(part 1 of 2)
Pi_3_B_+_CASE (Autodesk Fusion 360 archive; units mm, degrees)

design "Pi_3_B_+" references "Pi 3 B +"
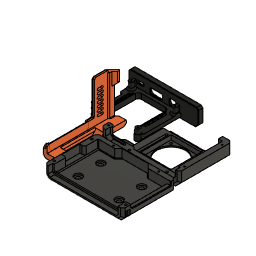
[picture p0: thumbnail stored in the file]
parameter "d10_Ref" = 24.193
parameter "d16_Ref" = 27.166
parameter "d18_Ref" = 29.088
parameter "d23_Ref" = -3
parameter "d27_Ref" = 6
parameter "d28_Ref" = 0
parameter "d52_Ref" = -1.4
parameter "d61_Ref" = -0.4
parameter "d62_Ref" = -1.053
parameter "d63_Ref" = -2
parameter "d65_Ref" = 0.172
parameter "d66_Ref" = -5
parameter "d67_Ref" = -2
parameter "d68_Ref" = -1
parameter "d89_Ref" = 0.75
parameter "d90_Ref" = 45 (= "Angle1")
parameter "d91_Ref" = 0 (= "Angle2")
parameter "d93_Ref" = -0.2
parameter "d94_Ref" = -0.1
parameter "d96_Ref" = 2
parameter "d103_Ref" = -0.1
parameter "d105_Ref" = -0.1
parameter "d106_Ref" = -0.1
parameter "d107_Ref" = -0.1
parameter "d109_Ref" = 2.6
parameter "d111_Ref" = 2.5
parameter "d112_Ref" = -0.1
parameter "d114_Ref" = -3
parameter "d116_Ref" = 0.5
parameter "d118_Ref" = 2
parameter "d119_Ref" = 5
parameter "d121_Ref" = -1
parameter "d122_Ref" = -2
parameter "d124_Ref" = 0.5
parameter "d128_Ref" = 2
parameter "d131_Ref" = 0.4
parameter "d132_Ref" = 0.5
parameter "d133_Ref" = 1
parameter "d134_Ref" = 3
parameter "d135_Ref" = 2.8
parameter "d147_Ref" = -0.4
parameter "d149_Ref" = -0.2
parameter "d151_Ref" = 0.4
parameter "d153_Ref" = 0.4
parameter "d155_Ref" = -0.2
parameter "d156_Ref" = -0.2
parameter "d157_Ref" = 0.399
parameter "d159_Ref" = 5
parameter "d161_Ref" = 45 (= "Angle1")
parameter "d162_Ref" = 0 (= "Angle2")
parameter "d163_Ref" = 45 (= "Angle1")
parameter "d164_Ref" = 0 (= "Angle2")
parameter "d165_Ref" = 2.5
parameter "d166_Ref" = 3
parameter "d167_Ref" = 3
parameter "d168_Ref" = 2.5
parameter "d169_Ref" = 1
parameter "d170_Ref" = 1
parameter "d171_Ref" = 1
parameter "d172_Ref" = 3
parameter "d173_Ref" = 1
parameter "d174_Ref" = 1
parameter "d206_Ref" = 0.4
parameter "d207_Ref" = 0.4
parameter "d208_Ref" = 8
parameter "d212_Ref" = 10
parameter "d213_Ref" = 3.3
parameter "d215_Ref" = -2
parameter "d217_Ref" = 0.5
parameter "d218_Ref" = 0.3
parameter "d219_Ref" = 0.3
parameter "d226_Ref" = -0.8
parameter "d227_Ref" = 10
parameter "d229_Ref" = 2.5
parameter "d232_Ref" = 2.5
parameter "d233_Ref" = 2
parameter "d239_Ref" = -8
parameter "d241_Ref" = 0.5
parameter "d242_Ref" = -3.536
parameter "d243_Ref" = 3
parameter "d12_Ref" = 20.9455
parameter "d14_Ref" = 28.705
parameter "d31_Ref" = 10
parameter "d32_Ref" = 2
parameter "d34_Ref" = 3
parameter "d35_Ref" = 20
parameter "d44_Ref" = -3
parameter "d49_Ref" = -11.7
parameter "d51_Ref" = 3
parameter "d53_Ref" = 3
parameter "d55_Ref" = 2
parameter "d57_Ref" = -1
parameter "d58_Ref" = 1
parameter "d60_Ref" = -0.4
parameter "d69_Ref" = 2.5
parameter "d70_Ref" = -1
parameter "d85_Ref" = 0.8
parameter "d86_Ref" = 0.75
parameter "d88_Ref" = 0.75
parameter "d152_Ref" = 0.3
parameter "d21_Ref" = 20.935
parameter "d38_Ref" = 60
parameter "d39_Ref" = 0
parameter "d40_Ref" = -5
parameter "d42_Ref" = -3.933
parameter "d43_Ref" = -1
parameter "d45_Ref" = 1
parameter "d56_Ref" = 1.4
parameter "d71_Ref" = 0.4
parameter "d75_Ref" = 2
parameter "d76_Ref" = 0.75
parameter "d77_Ref" = 1
parameter "d79_Ref" = -1
parameter "d80_Ref" = 1
parameter "d83_Ref" = 0.75
parameter "d84_Ref" = 0.75
parameter "d87_Ref" = 0.75
parameter "d92_Ref" = 0.2
parameter "d95_Ref" = 2
parameter "d98_Ref" = 2
parameter "d101_Ref" = 0.6
parameter "d102_Ref" = 2.6
parameter "d104_Ref" = 2
parameter "d220_Ref" = 2
parameter "d221_Ref" = 3
parameter "d222_Ref" = 0.2
parameter "d224_Ref" = 0.5
parameter "d225_Ref" = 0.8
parameter "d2_1_Ref" = 180
parameter "d3_Ref" = 180
parameter "d6_Ref" = 5
parameter "d7_Ref" = 5
parameter "d8_Ref" = 0
parameter "d59_Ref" = -1
parameter "d140_Ref" = 7.375
parameter "d141_Ref" = 2
parameter "d178_Ref" = -4.3752
parameter "d180_Ref" = 1.1
parameter "d181_Ref" = -4.3752
parameter "d183_Ref" = -0.1
parameter "d184_Ref" = 1
parameter "d185_Ref" = -2.291
parameter "d187_Ref" = 4
parameter "d188_Ref" = -1.625
parameter "d190_Ref" = 0
parameter "d191_Ref" = 10.23
parameter "d193_Ref" = 10
parameter "d194_Ref" = 2
parameter "d196_Ref" = 10
parameter "d197_Ref" = 2
parameter "d199_Ref" = 10
parameter "d200_Ref" = 2
parameter "d202_Ref" = 10
parameter "d203_Ref" = 2
parameter "d205_Ref" = 1
parameter "d261_Ref" = -10.895
parameter "d262_Ref" = -4.25
parameter "d263_Ref" = 2
parameter "d267_Ref" = -35
parameter "d268_Ref" = 0
parameter "d269_Ref" = 0.3
parameter "d287_Ref" = -5
parameter "d289_Ref" = 0.3
parameter "d292_Ref" = 35
parameter "d293_Ref" = 0
parameter "d294_Ref" = 0.3
parameter "d244_Ref" = 1
parameter "d250_Ref" = 6.4
parameter "d251_Ref" = 2
external_derived "ExternalDerived1" bodies "PI3 A/B_MOUNT  (1) (2)", "Body4", "TOP", "BOTTOM"
derived_instance "DerivedInstance1"
derived_instance "DerivedInstance2"
derived_instance "DerivedInstance3"
derived_instance "DerivedInstance4"
derived_instance "DerivedInstance1"
step "Arrange" envelopeLength 180 envelopeWidth 180 envelopeSeparation 0 separation 5 padding 5 offset 0
hole "Hole2" HoleDepth 5 HoleDiameter 5.3 CBDepth 2 CBDiameter 10 RefDim1 25 RefDim2 20
hole "Hole4" HoleDepth 5 HoleDiameter 5.3 CBDepth 2 CBDiameter 10 RefDim1 20 RefDim2 25
rectangular_pattern "R-Pattern2" uSpaceDistance 30 vSpaceDistance 0 bodies "BOTTOM"
rectangular_pattern "R-Pattern3" uSpaceDistance 30 vSpaceDistance 0 bodies "BOTTOM"
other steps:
derived_base_feature "Derived Base Feature1" bodies "BOTTOM"
derived_base_feature "Derived Base Feature1" bodies "Body4", "BOTTOM"
derived_base_feature "Derived Base Feature1" bodies "TOP", "BOTTOM"
derived_base_feature "Derived Base Feature1" bodies "PI3 A/B_MOUNT  (1) (2)", "BOTTOM"
derived_base_feature "Derived Base Feature1" bodies "BOTTOM"
create_component "CreateComponent1"
create_component "CreateComponent2"
create_component "CreateComponent3"
create_component "CreateComponent4"
create_component "CreateComponent5"
named bodies: "TOP", "BOTTOM", "PI3 A/B_MOUNT  (1) (2)", "Body4"

design "M3x5x4 heat-Insert"
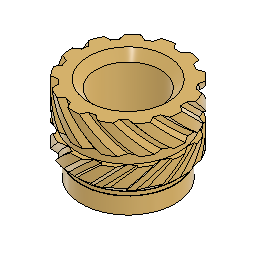
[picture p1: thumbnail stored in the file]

design "Pi 3 B +" references "M3x5x4 heat-Insert"
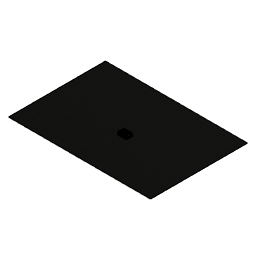
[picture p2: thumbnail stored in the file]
description: arrangementsContainer
base_feature "Base Feature1" bodies "TOP"
base_feature "Base Feature1" bodies "BOTTOM"
base_feature "Base Feature1"
base_feature "Base Feature1"
base_feature "Base Feature1"
base_feature "Base Feature1"
base_feature "Base Feature1"
base_feature "Base Feature1"
base_feature "Base Feature1"
base_feature "Base Feature1"
position "Position1"
sketch "Sketch1" plane through (0, 0, 0) normal (0, 0, 1) x axis (1, 0, 0)
  line L1 (753.1049, -468.8034) -> (-832.4959, -468.8034)
  line L2 (753.1049, 612.7156) -> (753.1049, -468.8034)
  line L3 (-832.4959, 612.7156) -> (753.1049, 612.7156)
  line L4 (-832.4959, -468.8034) -> (-832.4959, 612.7156)
  horizontal L1
  vertical L2
  horizontal L3
  vertical L4
extrude "Extrude1" new body sketch "Sketch1" against normal blind 1 bodies "base"
base_feature "Base Feature1" bodies "PI3 A/B_MOUNT  (1) (2)"
component_from_bodies "Body->Comp"
step "Arrange" envelopeLength 180 named "d2_1" envelopeWidth 180 envelopeSeparation 0 separation 5 padding 5 offset 0 bodies "TOP"
base_feature "Base Feature1"
position "Position2"
position "Position3"
delete_face "DeleteFace1"
base_feature "Base Feature1" bodies "PI_ZERO_MOUNT_1"
move_face "MoveFace1"
work_plane "WorkPlane2"
split "Split1" bodies "TOP (1)"
move "Move1"
move "Move2"
position "Position4"
align "Align1"
move "Move3"
extrude "Extrude1" add of existing geometry blind 24.193 bodies "TOP (1)"
delete_face "DeleteFace2"
delete_face "DeleteFace3"
delete_face "DeleteFace4"
align "Align1"
work_plane "WorkPlane3"
split "Split1" bodies "BOTTOM (1)"
move "Move1"
align "Align2"
move "Move2"
move "Move3"
extrude "Extrude1" add of existing geometry blind 20.9455 bodies "BOTTOM (1)"
work_plane "WorkPlane4"
split "Split2" bodies "BOTTOM (1)"
delete_face "DeleteFace1"
move "Move4"
split "Split2"
move "Move4"
align "Align3"
align "Align4"
align "Align1"
align "Align1"
delete_face "DeleteFace2"
delete_face "DeleteFace3"
extrude "Extrude2" add of existing geometry blind 28.705 bodies "BOTTOM (1)"
extrude "Extrude2" add of existing geometry blind 27.166 bodies "TOP"
extrude "Extrude3" add of existing geometry blind 29.088
align "Align1"
align "Align2"
align "Align3"
align "Align1"
align "Align1"
align "Align1"
align "Align1"
align "Align1"
work_plane "WorkPlane5" AlongDistance -25
split "Split1"
align "Align4"
extrude "Extrude1" add of existing geometry blind 20.935
move_face "MoveFace1"
move_face "MoveFace2"
move_face "MoveFace2"
delete_face "DeleteFace1"
delete_face "DeleteFace2"
sketch "Sketch3" plane through (0, 0, 18.6752) normal (0, 0, -1) x axis (1, 0, 0)
  line L1 (-40.9922, -30.131) -> (-40.9922, 26.269)
  line L2 (-39.8593, -30.131) -> (-40.9922, -30.131)
  line L3 (-39.8593, -21.931) -> (-39.8593, -30.131)
  line L4 (-37.6593, -19.731) -> (-39.8593, -21.931)
  line L5 (37.1513, -19.731) -> (-37.6593, -19.731)
  line L6 (37.9797, -18.9025) -> (37.1513, -19.731)
  line L7 (37.9797, 16.5519) -> (37.9797, -18.9025)
  line L8 (40.6719, 19.2441) -> (37.9797, 16.5519)
  line L9 (40.6719, 26.269) -> (40.6719, 19.2441)
  line L10 (4.9368, 26.269) -> (40.6719, 26.269)
  line L11 (6.4368, -14.231) -> (6.4368, 24.769)
  line L12 (3.4368, 24.769) -> (3.4368, -14.231)
  line L13 (-0.0632, 26.269) -> (4.9368, 26.269)
  line L14 (1.4368, -14.231) -> (1.4368, 24.769)
  line L15 (-1.5632, 24.769) -> (-1.5632, -14.231)
  line L16 (-5.0632, 26.269) -> (-0.0632, 26.269)
  line L17 (-3.5632, -15.231) -> (-3.5632, 24.769)
  line L18 (-6.5632, 24.769) -> (-6.5632, -15.231)
  line L19 (-10.0633, 26.269) -> (-5.0632, 26.269)
  line L20 (-9.9796, 26.2667) -> (-9.9797, 26.2667)
  line L21 (-8.5632, -17.231) -> (-8.5632, 24.769)
  line L22 (-9.9797, -18.7286) -> (-9.9796, -18.7286)
  line L23 (-11.5633, 24.769) -> (-11.5633, -17.231)
  line L24 (-15.0633, 26.269) -> (-10.0633, 26.269)
  line L25 (-13.5633, -17.231) -> (-13.5633, 24.769)
  line L26 (-16.5633, 24.769) -> (-16.5633, -17.231)
  line L27 (-20.0633, 26.269) -> (-15.0633, 26.269)
  line L28 (-18.5633, -15.231) -> (-18.5633, 24.769)
  line L29 (-21.5633, 24.769) -> (-21.5633, -15.231)
  line L30 (-25.0633, 26.269) -> (-20.0633, 26.269)
  line L31 (-23.5633, -14.231) -> (-23.5633, 24.769)
  line L32 (-26.5633, 24.769) -> (-26.5633, -14.231)
  line L33 (-30.0633, 26.269) -> (-25.0633, 26.269)
  line L34 (-28.5633, -14.231) -> (-28.5633, 24.769)
  line L35 (-31.5633, 24.769) -> (-31.5633, -14.231)
  line L36 (-35.0633, 26.269) -> (-30.0633, 26.269)
  line L37 (-33.5633, -14.231) -> (-33.5633, 24.769)
  line L38 (-36.5633, 24.769) -> (-36.5633, -14.231)
  line L39 (-40.9922, 26.269) -> (-35.0633, 26.269)
  line L40 (-32.6085, -18.7224) -> (10.2712, -18.7224)
  line L41 (-32.6085, 24.769) -> (-32.6085, -18.7224)
  line L42 (10.2712, 24.769) -> (-32.6085, 24.769)
  line L43 (10.2712, -18.7224) -> (10.2712, 24.769)
  arc A1 centre (4.9368, 24.769) radius 1.5 clockwise from (4.9368, 26.269) to (6.4368, 24.769)
  arc A2 centre (4.9368, -14.231) radius 1.5 clockwise from (6.4368, -14.231) to (3.4368, -14.231)
  arc A3 centre (4.9368, 24.769) radius 1.5 clockwise from (3.4368, 24.769) to (4.9368, 26.269)
  arc A4 centre (-0.0632, 24.769) radius 1.5 clockwise from (-0.0632, 26.269) to (1.4368, 24.769)
  arc A5 centre (-0.0632, -14.231) radius 1.5 clockwise from (1.4368, -14.231) to (-1.5632, -14.231)
  arc A6 centre (-0.0632, 24.769) radius 1.5 clockwise from (-1.5632, 24.769) to (-0.0632, 26.269)
  arc A7 centre (-5.0632, 24.769) radius 1.5 clockwise from (-5.0632, 26.269) to (-3.5632, 24.769)
  arc A8 centre (-5.0632, -15.231) radius 1.5 clockwise from (-3.5632, -15.231) to (-6.5632, -15.231)
  arc A9 centre (-5.0632, 24.769) radius 1.5 clockwise from (-6.5632, 24.769) to (-5.0632, 26.269)
  arc A10 centre (-10.0633, 24.769) radius 1.5 clockwise from (-10.0633, 26.269) to (-9.9797, 26.2667)
  arc A11 centre (-10.0632, 24.769) radius 1.5 clockwise from (-9.9796, 26.2667) to (-8.5632, 24.769)
  arc A12 centre (-10.0632, -17.231) radius 1.5 clockwise from (-8.5632, -17.231) to (-9.9796, -18.7286)
  arc A13 centre (-10.0633, -17.231) radius 1.5 clockwise from (-9.9797, -18.7286) to (-11.5633, -17.231)
  arc A14 centre (-10.0633, 24.769) radius 1.5 clockwise from (-11.5633, 24.769) to (-10.0633, 26.269)
  arc A15 centre (-15.0633, 24.769) radius 1.5 clockwise from (-15.0633, 26.269) to (-13.5633, 24.769)
  arc A16 centre (-15.0633, -17.231) radius 1.5 clockwise from (-13.5633, -17.231) to (-16.5633, -17.231)
  arc A17 centre (-15.0633, 24.769) radius 1.5 clockwise from (-16.5633, 24.769) to (-15.0633, 26.269)
  arc A18 centre (-20.0633, 24.769) radius 1.5 clockwise from (-20.0633, 26.269) to (-18.5633, 24.769)
  arc A19 centre (-20.0633, -15.231) radius 1.5 clockwise from (-18.5633, -15.231) to (-21.5633, -15.231)
  arc A20 centre (-20.0633, 24.769) radius 1.5 clockwise from (-21.5633, 24.769) to (-20.0633, 26.269)
  arc A21 centre (-25.0633, 24.769) radius 1.5 clockwise from (-25.0633, 26.269) to (-23.5633, 24.769)
  arc A22 centre (-25.0633, -14.231) radius 1.5 clockwise from (-23.5633, -14.231) to (-26.5633, -14.231)
  arc A23 centre (-25.0633, 24.769) radius 1.5 clockwise from (-26.5633, 24.769) to (-25.0633, 26.269)
  arc A24 centre (-30.0633, 24.769) radius 1.5 clockwise from (-30.0633, 26.269) to (-28.5633, 24.769)
  arc A25 centre (-30.0633, -14.231) radius 1.5 clockwise from (-28.5633, -14.231) to (-31.5633, -14.231)
  arc A26 centre (-30.0633, 24.769) radius 1.5 clockwise from (-31.5633, 24.769) to (-30.0633, 26.269)
  arc A27 centre (-35.0633, 24.769) radius 1.5 clockwise from (-35.0633, 26.269) to (-33.5633, 24.769)
  arc A28 centre (-35.0633, -14.231) radius 1.5 clockwise from (-33.5633, -14.231) to (-36.5633, -14.231)
  arc A29 centre (-35.0633, 24.769) radius 1.5 clockwise from (-36.5633, 24.769) to (-35.0633, 26.269)
  horizontal L40
  vertical L41
  horizontal L42
  vertical L43
extrude "Extrude4" add sketch "Sketch3" profile of L11 A2 L12 L14 A5 L15 L17 A8 L18 L21 A12 A13 L23 L25 A16 L26 L28 A19 L29 L31 A22 L32 L34 A25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 against normal blind 3
delete_face "DeleteFace3"
delete_face "DeleteFace4"
delete_face "DeleteFace5"
delete_face "DeleteFace6"
delete_face "DeleteFace7"
delete_face "DeleteFace8"
rectangular_pattern "R-Pattern1" uSpaceDistance 6 vSpaceDistance 0
position "Position5"
work_plane "WorkPlane6" AlongDistance 2
work_plane "WorkPlane7" AlongDistance 2
move_face "MoveFace1"
move_face "MoveFace2"
move_face "MoveFace3"
hole "Hole1" HoleDepth 10 HoleDiameter 2 RefDim1 3 RefDim2 20
work_axis "WorkAxis1"
move_face "MoveFace4"
work_axis "WorkAxis3"
move_face "MoveFace3"
rectangular_pattern "R-Pattern1" uSpaceDistance 60 vSpaceDistance 0
position "Position6"
position "Position7"
delete_face "DeleteFace1"
delete_face "DeleteFace2"
delete_face "DeleteFace3"
extrude "Extrude2" cut of existing geometry blind -5
delete_face "DeleteFace4"
offset_faces "OffsetFaces1" distance -3.933
offset_faces "OffsetFaces2" distance -1
move_face "MoveFace4"
delete_face "DeleteFace5"
delete_face "DeleteFace4"
delete_face "DeleteFace5"
delete_face "DeleteFace6"
offset_faces "OffsetFaces1" distance -3
delete_face "DeleteFace7"
chamfer "Chamfer2" distance 1
work_plane "WorkPlane8" AlongDistance 1
move_face "MoveFace2"
move_face "MoveFace5"
work_plane "WorkPlane9" AlongDistance 0
sketch "Sketch4" plane through (0, 0, 16.7) normal (0, 0, 1) x axis (-1, 0, 0)
  line L1 (-45.1398, 29) -> (-45.1398, 24.4)
  line L2 (-45.7598, 29) -> (-45.1398, 29)
  line L3 (-45.7598, 35) -> (-45.7598, 29)
  line L4 (-49.1398, 35) -> (-45.7598, 35)
  line L5 (-52.1398, 32) -> (-49.1398, 35)
  line L6 (-52.1398, 21.7542) -> (-52.1398, 32)
  line L7 (-49.1398, 20) -> (-49.1398, 25)
  line L8 (-52.1398, -32) -> (-52.1398, 22.2)
  line L9 (-52.1398, 20) -> (-49.1398, 20)
  line L10 (-45.1398, 20) -> (-45.1398, 24.4)
  line L11 (-49.1398, 20) -> (-45.1398, 20)
  circle C1 centre (-49.1398, 25) radius 1.4
  arc A1 centre (-49.1398, 24.4) radius 4 clockwise from (-45.1398, 24.4) to (-52.1398, 21.7542)
  point P2 (-49.1398, 25)
  point P11 (-49.1398, 25)
  point P15 (-52.1398, 20)
  point P3 (-45.1398, 24.4)
  point P16 (-45.1398, 24.4)
  point P12 (-49.1398, 20)
  coincident P2 P11
  vertical L7
  coincident L8 P15
  perpendicular L8 L9
  coincident P3 P16
  perpendicular L9 L10
  perpendicular L7 L11
  dimension "d48" distance P11 P12 = 5
extrude "Extrude3" add sketch "Sketch4" profile of A1 L7 L10 L11 against normal blind 11.7
offset_faces "OffsetFaces2" distance 3
delete_face "DeleteFace8"
delete_face "DeleteFace9"
move_face "MoveFace6"
delete_face "DeleteFace10"
delete_face "DeleteFace11"
delete_face "DeleteFace12"
move_face "MoveFace7"
work_axis "WorkAxis4"
move_face "MoveFace4"
offset_faces "OffsetFaces1" distance -1.4
chamfer "Chamfer2" distance 3
fillet "Fillet1" radius 2
offset_faces "OffsetFaces3" distance 1.4
offset_faces "OffsetFaces3" distance -1
offset_faces "OffsetFaces4" distance 1
position "Position8"
offset_faces "OffsetFaces1" distance -1
offset_faces "OffsetFaces5" distance -0.4
offset_faces "OffsetFaces3" distance -1.053
sketch "Sketch5" plane through (0, -27, 0) normal (0, 1, 0) x axis (-1, 0, 0)
  line L1 (-40.8321, 30.4) -> (-13.0969, 30.4)
  line L2 (-45.1398, 26.0922) -> (-40.8321, 30.4)
  line L3 (-45.1398, 24.753) -> (-45.1398, 26.0922)
  line L4 (-41.3928, 28.5) -> (-45.1398, 24.753)
  line L5 (39.9036, 28.5) -> (-41.3928, 28.5)
  line L6 (45.1398, 23.2638) -> (39.9036, 28.5)
  line L7 (45.1398, 26.0922) -> (45.1398, 23.2638)
  line L8 (40.8321, 30.4) -> (45.1398, 26.0922)
  line L9 (34.9031, 30.4) -> (40.8321, 30.4)
  line L10 (28.9031, 30.4) -> (34.9031, 30.4)
  line L11 (22.9031, 30.4) -> (28.9031, 30.4)
  line L12 (16.9031, 30.4) -> (22.9031, 30.4)
  line L13 (10.9031, 30.4) -> (16.9031, 30.4)
  line L14 (4.9031, 30.4) -> (10.9031, 30.4)
  line L15 (-1.0969, 30.4) -> (4.9031, 30.4)
  line L16 (-7.0969, 30.4) -> (-1.0969, 30.4)
  line L17 (-13.0969, 30.4) -> (-7.0969, 30.4)
  line L18 (-21.1686, 27.0881) -> (-42.8047, 27.0881)
  line L19 (-21.0388, 27.4) -> (-20.0388, 28.4)
  line L20 (-20.5388, 27.9) -> (-20.0388, 28.4)
  line L21 (-22.4602, 25.9787) -> (-20.5388, 27.9)
  line L22 (-21.0388, 27.4) -> (-22.4602, 25.9787)
  line L23 (-45.1398, 24.753) -> (-41.3928, 28.5)
  line L24 (39.9036, 28.5) -> (-41.3928, 28.5)
  line L25 (-41.4928, 28.4) -> (-20.0388, 28.4)
  point P19 (-42.8047, 27.0881)
  point P21 (-20.0388, 28.4)
  point P28 (-20.0388, 28.4)
  point P29 (-41.4928, 28.4)
  coincident L4 P19
  parallel L5 L18
  coincident P21 P28
  coincident L23 P29
  parallel L24 L25
extrude "Extrude5" add sketch "Sketch5" profile of L4 L18 L19 L20 L21 L22 L23 L25 against normal blind 2
offset_faces "OffsetFaces4" distance 0.172
offset_faces "OffsetFaces5" distance -5
delete_face "DeleteFace9"
offset_faces "OffsetFaces6" distance -2
offset_faces "OffsetFaces7" distance -1
chamfer "Chamfer3" distance 2.5
offset_faces "OffsetFaces6" distance -1
move_face "MoveFace3"
move_face "MoveFace4"
move_face "MoveFace5"
position "Position9"
offset_faces "OffsetFaces4" distance 0.4
sketch "Sketch6" plane through (0, -24.4, 0) normal (0, 1, 0) x axis (-1, 0, 0)
  line L1 (-44.9031, 33.4) -> (-40.0398, 33.4)
  line L2 (-52.1398, 26.1633) -> (-44.9031, 33.4)
  line L3 (-52.1398, 16.7) -> (-52.1398, 26.1633)
  line L4 (-47.1398, 16.7) -> (-52.1398, 16.7)
  line L5 (-47.1398, 26.9206) -> (-47.1398, 16.7)
  line L6 (-43.6605, 30.4) -> (-47.1398, 26.9206)
  line L7 (-38.1398, 30.4) -> (-43.6605, 30.4)
  line L8 (-38.1398, 31.6) -> (-38.1398, 30.4)
  line L9 (-40.0398, 31.6) -> (-38.1398, 31.6)
  line L10 (-40.0398, 33.4) -> (-40.0398, 31.6)
  line L11 (-51.3825, 26.9206) -> (-47.1398, 26.9206)
  line L12 (-47.1398, 29.0252) -> (-42.2068, 29.0252)
  line L13 (-49.2779, 29.0252) -> (-47.1398, 29.0252)
  line L14 (-49.2779, 29.0252) -> (-49.2779, 29.0252)
  line L15 (-42.2068, 29.0252) -> (-49.2779, 29.0252)
  line L16 (-42.2068, 29.0252) -> (-42.2068, 29.0252)
  point P7 (-47.1398, 26.9206)
  point P12 (-47.1398, 26.9206)
  point P13 (-51.3825, 26.9206)
  coincident P7 P12
  coincident L2 P13
  perpendicular L5 L11
extrude "Extrude2" new body sketch "Sketch6" profile of L2 L6 L11 L12 L13 L15 blind 15 from offset 0.1
combine "Combine1"
chamfer "Chamfer3" distance 2
delete_face "DeleteFace6"
offset_faces "OffsetFaces5" distance 0.75
extrude "Extrude3" add of existing geometry blind 1
delete_face "DeleteFace7"
offset_faces "OffsetFaces6" distance -1
extrude "Extrude4" add of existing geometry blind 1
delete_face "DeleteFace8"
delete_face "DeleteFace9"
delete_face "DeleteFace10"
chamfer "Chamfer5" distance 0.75
delete_face "DeleteFace11"
delete_face "DeleteFace12"
delete_face "DeleteFace13"
chamfer "Chamfer6" distance 0.75
offset_faces "OffsetFaces7" distance 0.8
delete_face "DeleteFace14"
chamfer "Chamfer4" distance 0.75
chamfer "Chamfer7" distance 0.75
split "Split3" bodies "TOP (1) (1)", "TOP (1) (2)"
chamfer "Chamfer5" distance 0.75
combine "Combine1" bodies "TOP (1) (1)", "TOP (1) (2)"
draft "Draft1" "d90" 45 (= "Angle1") "d91" 0 (= "Angle2")
combine "Combine2"
offset_faces "OffsetFaces7" distance 0.2
offset_faces "OffsetFaces8" distance -0.2
move_face "MoveFace5"
move_face "MoveFace5"
offset_faces "OffsetFaces9" distance -0.1
chamfer "Chamfer8" distance 2
chamfer "Chamfer3" distance 2
sketch "Sketch7" plane through (0, -24.3, 0) normal (0, -1, 0) x axis (1, 0, 0)
  line L1 (25.1398, 30.4) -> (25.1398, 31.6)
  line L2 (40.8321, 30.4) -> (25.1398, 30.4)
  line L3 (41.2068, 30.0252) -> (40.8321, 30.4)
  line L4 (44.0353, 30.0252) -> (41.2068, 30.0252)
  line L5 (45.0353, 29.0252) -> (44.0353, 30.0252)
  line L6 (47.8898, 26.1706) -> (45.0353, 29.0252)
  line L7 (47.8898, 25.1706) -> (47.8898, 26.1706)
  line L8 (51.3825, 25.1706) -> (47.8898, 25.1706)
  line L9 (52.1325, 25.9206) -> (51.3825, 25.1706)
  line L10 (52.1325, 26.1706) -> (52.1325, 25.9206)
  line L11 (44.9031, 33.4) -> (52.1325, 26.1706)
  line L12 (27.0398, 33.4) -> (44.9031, 33.4)
  line L13 (27.0398, 31.6) -> (27.0398, 33.4)
  line L14 (25.1398, 31.6) -> (27.0398, 31.6)
  line L15 (40.1398, 31.6) -> (25.1398, 31.6)
  line L16 (40.1398, 30.4) -> (40.1398, 31.6)
  line L17 (25.1398, 30.4) -> (40.1398, 30.4)
  line L18 (25.1398, 31.6) -> (25.1398, 30.4)
  point P2 (25.1398, 31.6)
  point P16 (25.1398, 31.6)
  point P17 (40.1398, 31.6)
  horizontal L15
  vertical L16
  horizontal L17
  vertical L18
  coincident P2 P16
  dimension "d97" distance P16 P17 = 15
extrude "Extrude5" add sketch "Sketch7" profile of L1 L2 L14 L15 L16 L17 L18 along normal blind 2
delete_face "DeleteFace15"
delete_face "DeleteFace16"
delete_face "DeleteFace17"
delete_face "DeleteFace18"
offset_faces "OffsetFaces8" distance 0.6
chamfer "Chamfer10" distance 2.6
combine "Combine2"
offset_faces "OffsetFaces10" distance -0.1
offset_faces "OffsetFaces9" distance 2
combine "Combine3"
offset_faces "OffsetFaces11" distance -0.1
offset_faces "OffsetFaces12" distance -0.1
offset_faces "OffsetFaces13" distance -0.1
sketch "Sketch8" plane through (0, -27, 0) normal (0, 1, 0) x axis (-1, 0, 0)
  line L1 (-40.4097, 31.7) -> (-25.0398, 31.7)
  line L2 (-40.4097, 30.4) -> (-40.4097, 31.7)
  line L3 (-43.6605, 30.4) -> (-40.4097, 30.4)
  line L4 (-45.1398, 28.9206) -> (-43.6605, 30.4)
  line L5 (-45.1398, 26.1672) -> (-45.1398, 28.9206)
  line L6 (-44.2189, 27.0881) -> (-45.1398, 26.1672)
  line L7 (-28.4218, 27.0881) -> (-44.2189, 27.0881)
  line L8 (-27.0099, 28.5) -> (-28.4218, 27.0881)
  line L9 (39.9036, 28.5) -> (-27.0099, 28.5)
  line L10 (45.1398, 23.2638) -> (39.9036, 28.5)
  line L11 (45.1398, 26.0922) -> (45.1398, 23.2638)
  line L12 (40.8321, 30.4) -> (45.1398, 26.0922)
  line L13 (34.9031, 30.4) -> (40.8321, 30.4)
  line L14 (28.9031, 30.4) -> (34.9031, 30.4)
  line L15 (22.9031, 30.4) -> (28.9031, 30.4)
  line L16 (16.9031, 30.4) -> (22.9031, 30.4)
  line L17 (10.9031, 30.4) -> (16.9031, 30.4)
  line L18 (4.9031, 30.4) -> (10.9031, 30.4)
  line L19 (-1.0969, 30.4) -> (4.9031, 30.4)
  line L20 (-7.0969, 30.4) -> (-1.0969, 30.4)
  line L21 (-13.0969, 30.4) -> (-7.0969, 30.4)
  line L22 (-25.0398, 30.4) -> (-13.0969, 30.4)
  line L23 (-25.0398, 31.7) -> (-25.0398, 30.4)
  line L24 (-18.6605, 30.4) -> (-43.6605, 30.4)
  line L25 (-18.6605, 28.5) -> (-18.6605, 30.4)
  line L26 (-45.5605, 28.5) -> (-18.6605, 28.5)
  line L27 (-43.6605, 30.4) -> (-45.5605, 28.5)
  point P5 (-43.6605, 30.4)
  point P25 (-43.6605, 30.4)
  point P27 (-18.6605, 28.5)
  point P26 (-18.6605, 30.4)
  coincident P5 P25
  parallel L22 L24
  coincident L9 P27
  perpendicular L9 L25
  perpendicular L5 L26
  parallel L4 L27
  dimension "d108" distance P25 P26 = 25
extrude "Extrude6" add sketch "Sketch8" profile of L3 L4 L5 L9 L22 L24 L25 L26 L27 along normal blind 2.6
delete_face "DeleteFace10"
chamfer "Chamfer4" distance 2.5
delete_face "DeleteFace11"
offset_faces "OffsetFaces14" distance -0.1
sketch "Sketch9" plane through (0, 0, 33.4) normal (0, 0, 1) x axis (-1, 0, 0)
  line L1 (-24.9398, -18.9172) -> (-24.9398, 22.4)
  line L2 (-22.957, -20.9) -> (-24.9398, -18.9172)
  line L3 (36.5406, -20.9) -> (-22.957, -20.9)
  line L4 (39.6992, -24.0586) -> (36.5406, -20.9)
  line L5 (39.6992, -32) -> (39.6992, -24.0586)
  line L6 (44.9031, -32) -> (39.6992, -32)
  line L7 (44.9031, 32) -> (44.9031, -32)
  line L8 (34.6979, 32) -> (44.9031, 32)
  line L9 (34.6979, 31) -> (34.6979, 32)
  line L10 (28.8979, 32) -> (28.8979, 31)
  line L11 (-24.9412, 32) -> (28.8979, 32)
  line L12 (-24.9412, 31) -> (-24.9412, 32)
  line L13 (-30.7412, 32) -> (-30.7412, 31)
  line L14 (-44.9031, 32) -> (-30.7412, 32)
  line L15 (-44.9031, 24.4) -> (-44.9031, 32)
  line L16 (-26.9398, 24.4) -> (-44.9031, 24.4)
  line L17 (-24.9398, 22.4) -> (-26.9398, 24.4)
  line L18 (-9.0969, 25.5) -> (-9.0969, -13.5)
  line L19 (-5.0969, -13.5) -> (-5.0969, 25.5)
  line L20 (2.9031, 25.5) -> (2.9031, -13.5)
  line L21 (6.9031, -13.5) -> (6.9031, 25.5)
  line L22 (14.9031, 25.5) -> (14.9031, -13.5)
  line L23 (18.9031, -13.5) -> (18.9031, 25.5)
  line L24 (26.9031, 25.5) -> (26.9031, -13.5)
  line L25 (30.9031, -13.5) -> (30.9031, 25.5)
  line L26 (36.9031, -13.5) -> (36.9031, 25.5)
  line L27 (32.9031, 25.5) -> (32.9031, -13.5)
  line L28 (20.9031, 25.5) -> (20.9031, -13.5)
  line L29 (24.9031, -13.5) -> (24.9031, 25.5)
  line L30 (8.9031, 25.5) -> (8.9031, -13.5)
  line L31 (12.9031, -13.5) -> (12.9031, 25.5)
  line L32 (-3.0969, 25.5) -> (-3.0969, -13.5)
  line L33 (0.9031, -13.5) -> (0.9031, 25.5)
  line L34 (-15.0969, 25.5) -> (-15.0969, -13.5)
  line L35 (-11.0969, -13.5) -> (-11.0969, 25.5)
  line L36 (32.9031, -13.5) -> (32.9031, 25.5)
  line L37 (36.9031, 25.5) -> (36.9031, -13.5)
  line L38 (34.9031, -8.5) -> (34.9031, -13.5)
  line L39 (36.4031, -13.5) -> (36.4031, 25.5)
  line L40 (36.9031, -8.5) -> (32.9031, -8.5)
  arc A1 centre (31.7979, 31) radius 2.9 clockwise from (34.6979, 31) to (28.8979, 31)
  arc A2 centre (-27.8412, 31) radius 2.9 clockwise from (-24.9412, 31) to (-30.7412, 31)
  arc A3 centre (-7.0969, 25.5) radius 2 clockwise from (-9.0969, 25.5) to (-5.0969, 25.5)
  arc A4 centre (-7.0969, -13.5) radius 2 clockwise from (-5.0969, -13.5) to (-9.0969, -13.5)
  arc A5 centre (4.9031, 25.5) radius 2 clockwise from (2.9031, 25.5) to (6.9031, 25.5)
  arc A6 centre (4.9031, -13.5) radius 2 clockwise from (6.9031, -13.5) to (2.9031, -13.5)
  arc A7 centre (16.9031, 25.5) radius 2 clockwise from (14.9031, 25.5) to (18.9031, 25.5)
  arc A8 centre (16.9031, -13.5) radius 2 clockwise from (18.9031, -13.5) to (14.9031, -13.5)
  arc A9 centre (28.9031, 25.5) radius 2 clockwise from (26.9031, 25.5) to (30.9031, 25.5)
  arc A10 centre (28.9031, -13.5) radius 2 clockwise from (30.9031, -13.5) to (26.9031, -13.5)
  arc A11 centre (34.9031, 25.5) radius 2 clockwise from (32.9031, 25.5) to (36.9031, 25.5)
  arc A12 centre (34.9031, -13.5) radius 2 clockwise from (36.9031, -13.5) to (32.9031, -13.5)
  arc A13 centre (22.9031, 25.5) radius 2 clockwise from (20.9031, 25.5) to (24.9031, 25.5)
  arc A14 centre (22.9031, -13.5) radius 2 clockwise from (24.9031, -13.5) to (20.9031, -13.5)
  arc A15 centre (10.9031, 25.5) radius 2 clockwise from (8.9031, 25.5) to (12.9031, 25.5)
  arc A16 centre (10.9031, -13.5) radius 2 clockwise from (12.9031, -13.5) to (8.9031, -13.5)
  arc A17 centre (-1.0969, 25.5) radius 2 clockwise from (-3.0969, 25.5) to (0.9031, 25.5)
  arc A18 centre (-1.0969, -13.5) radius 2 clockwise from (0.9031, -13.5) to (-3.0969, -13.5)
  arc A19 centre (-13.0969, 25.5) radius 2 clockwise from (-15.0969, 25.5) to (-11.0969, 25.5)
  arc A20 centre (-13.0969, -13.5) radius 2 clockwise from (-11.0969, -13.5) to (-15.0969, -13.5)
  arc A21 centre (34.9031, -13.5) radius 2 clockwise from (36.9031, -13.5) to (32.9031, -13.5)
  circle C1 centre (34.9031, -8.5) radius 2
  circle C2 centre (34.9031, -8.5) radius 1.5
  point P52 (34.9031, -13.5)
  point P82 (34.9031, -13.5)
  point P83 (34.9031, -8.5)
  point P84 (34.9031, -8.5)
  point P85 (34.9031, -8.5)
  point P88 (32.9031, -8.5)
  point P89 (36.9031, -8.5)
  coincident P52 P82
  parallel L26 L38
  coincident P83 P84
  tangent L37 C1
  coincident P83 P85
  tangent C2 L39
  coincident L27 P88
  coincident C1 P88
  coincident L26 P89
  coincident C1 P89
  perpendicular L26 L40
  dimension "d113" distance P82 P83 = 5
extrude "Extrude7" add sketch "Sketch9" profile of L26 A12 L27 A21 L36 L37 C1 C2 L39 L40 against normal blind 3
chamfer "Chamfer5" distance 0.5
sketch "Sketch10" plane through (0, 0, 33.4) normal (0, 0, 1) x axis (-1, 0, 0)
  line L1 (32.9031, 25.5) -> (32.9031, -8.5)
  line L2 (36.9031, -8.5) -> (36.9031, 25.5)
  line L3 (-24.9398, -18.9172) -> (-24.9398, 22.4)
  line L4 (-22.957, -20.9) -> (-24.9398, -18.9172)
  line L5 (36.5406, -20.9) -> (-22.957, -20.9)
  line L6 (39.6992, -24.0586) -> (36.5406, -20.9)
  line L7 (39.6992, -32) -> (39.6992, -24.0586)
  line L8 (44.9031, -32) -> (39.6992, -32)
  line L9 (44.9031, 32) -> (44.9031, -32)
  line L10 (34.6978, 32) -> (44.9031, 32)
  line L11 (34.6978, 31) -> (34.6978, 32)
  line L12 (28.8978, 32) -> (28.8978, 31)
  line L13 (-24.9412, 32) -> (28.8978, 32)
  line L14 (-24.9412, 31) -> (-24.9412, 32)
  line L15 (-30.7412, 32) -> (-30.7412, 31)
  line L16 (-44.9031, 32) -> (-30.7412, 32)
  line L17 (-44.9031, 24.4) -> (-44.9031, 32)
  line L18 (-26.9398, 24.4) -> (-44.9031, 24.4)
  line L19 (-24.9398, 22.4) -> (-26.9398, 24.4)
  line L20 (-9.0969, 25.5) -> (-9.0969, -13.5)
  line L21 (-5.0969, -13.5) -> (-5.0969, 25.5)
  line L22 (2.9031, 25.5) -> (2.9031, -13.5)
  line L23 (6.9031, -13.5) -> (6.9031, 25.5)
  line L24 (14.9031, 25.5) -> (14.9031, -13.5)
  line L25 (18.9031, -13.5) -> (18.9031, 25.5)
  line L26 (26.9031, 25.5) -> (26.9031, -13.5)
  line L27 (30.9031, -13.5) -> (30.9031, 25.5)
  line L28 (20.9031, 25.5) -> (20.9031, -13.5)
  line L29 (24.9031, -13.5) -> (24.9031, 25.5)
  line L30 (8.9031, 25.5) -> (8.9031, -13.5)
  line L31 (12.9031, -13.5) -> (12.9031, 25.5)
  line L32 (-3.0969, 25.5) -> (-3.0969, -13.5)
  line L33 (0.9031, -13.5) -> (0.9031, 25.5)
  line L34 (-15.0969, 25.5) -> (-15.0969, -13.5)
  line L35 (-11.0969, -13.5) -> (-11.0969, 25.5)
  line L36 (34.9031, -15.5) -> (34.9031, -8.5)
  arc A1 centre (34.9031, -8.5) radius 2 clockwise from (36.9031, -8.5) to (32.9031, -8.5)
  arc A2 centre (34.9031, 25.5) radius 2 clockwise from (32.9031, 25.5) to (36.9031, 25.5)
  arc A3 centre (31.7978, 31) radius 2.9 clockwise from (34.6978, 31) to (28.8978, 31)
  arc A4 centre (-27.8412, 31) radius 2.9 clockwise from (-24.9412, 31) to (-30.7412, 31)
  arc A5 centre (-7.0969, 25.5) radius 2 clockwise from (-9.0969, 25.5) to (-5.0969, 25.5)
  arc A6 centre (-7.0969, -13.5) radius 2 clockwise from (-5.0969, -13.5) to (-9.0969, -13.5)
  arc A7 centre (4.9031, 25.5) radius 2 clockwise from (2.9031, 25.5) to (6.9031, 25.5)
  arc A8 centre (4.9031, -13.5) radius 2 clockwise from (6.9031, -13.5) to (2.9031, -13.5)
  arc A9 centre (16.9031, 25.5) radius 2 clockwise from (14.9031, 25.5) to (18.9031, 25.5)
  arc A10 centre (16.9031, -13.5) radius 2 clockwise from (18.9031, -13.5) to (14.9031, -13.5)
  arc A11 centre (28.9031, 25.5) radius 2 clockwise from (26.9031, 25.5) to (30.9031, 25.5)
  arc A12 centre (28.9031, -13.5) radius 2 clockwise from (30.9031, -13.5) to (26.9031, -13.5)
  arc A13 centre (22.9031, 25.5) radius 2 clockwise from (20.9031, 25.5) to (24.9031, 25.5)
  arc A14 centre (22.9031, -13.5) radius 2 clockwise from (24.9031, -13.5) to (20.9031, -13.5)
  arc A15 centre (10.9031, 25.5) radius 2 clockwise from (8.9031, 25.5) to (12.9031, 25.5)
  arc A16 centre (10.9031, -13.5) radius 2 clockwise from (12.9031, -13.5) to (8.9031, -13.5)
  arc A17 centre (-1.0969, 25.5) radius 2 clockwise from (-3.0969, 25.5) to (0.9031, 25.5)
  arc A18 centre (-1.0969, -13.5) radius 2 clockwise from (0.9031, -13.5) to (-3.0969, -13.5)
  arc A19 centre (-13.0969, 25.5) radius 2 clockwise from (-15.0969, 25.5) to (-11.0969, 25.5)
  arc A20 centre (-13.0969, -13.5) radius 2 clockwise from (-11.0969, -13.5) to (-15.0969, -13.5)
  point P4 (34.9031, -8.5)
  point P77 (34.9031, -8.5)
  point P78 (34.9031, -15.5)
  point P79 (34.9031, -15.5)
  coincident P4 P77
  perpendicular L5 L36
  coincident P78 P79
  dimension "d117" distance P77 P78 = 7
hole "Hole1" HoleDepth 2 HoleDiameter 5
extrude "Extrude8" add of existing geometry blind -2 from offset -1
offset_faces "OffsetFaces15" distance 0.5
sketch "Sketch12" plane through (0, 0, 30.4) normal (0, 0, -1) x axis (1, 0, 0)
  line L1 (-36.4031, 25.5) -> (-36.4031, -8.5)
  line L2 (-40.8321, 27) -> (-34.9031, 27)
  line L3 (-40.8321, -29.4) -> (-40.8321, 27)
  line L4 (-39.6992, -29.4) -> (-40.8321, -29.4)
  line L5 (-39.6992, -21.0586) -> (-39.6992, -29.4)
  line L6 (-37.5406, -18.9) -> (-39.6992, -21.0586)
  line L7 (22.27, -18.9) -> (-37.5406, -18.9)
  line L8 (23.0398, -18.1302) -> (22.27, -18.9)
  line L9 (23.0398, 24.4) -> (23.0398, -18.1302)
  line L10 (18.7605, 24.4) -> (23.0398, 24.4)
  line L11 (16.1605, 27) -> (18.7605, 24.4)
  line L12 (13.0969, 27) -> (16.1605, 27)
  line L13 (14.5969, -13.5) -> (14.5969, 25.5)
  line L14 (11.5969, 25.5) -> (11.5969, -13.5)
  line L15 (7.0969, 27) -> (13.0969, 27)
  line L16 (8.5969, -13.5) -> (8.5969, 25.5)
  line L17 (5.5969, 25.5) -> (5.5969, -13.5)
  line L18 (1.0969, 27) -> (7.0969, 27)
  line L19 (2.5969, -13.5) -> (2.5969, 25.5)
  line L20 (-0.4031, 25.5) -> (-0.4031, -13.5)
  line L21 (-4.9031, 27) -> (1.0969, 27)
  line L22 (-3.4031, -13.5) -> (-3.4031, 25.5)
  line L23 (-6.4031, 25.5) -> (-6.4031, -13.5)
  line L24 (-10.9031, 27) -> (-4.9031, 27)
  line L25 (-9.4031, -13.5) -> (-9.4031, 25.5)
  line L26 (-12.4031, 25.5) -> (-12.4031, -13.5)
  line L27 (-16.9031, 27) -> (-10.9031, 27)
  line L28 (-15.4031, -13.5) -> (-15.4031, 25.5)
  line L29 (-18.4031, 25.5) -> (-18.4031, -13.5)
  line L30 (-22.9031, 27) -> (-16.9031, 27)
  line L31 (-21.4031, -13.5) -> (-21.4031, 25.5)
  line L32 (-24.4031, 25.5) -> (-24.4031, -13.5)
  line L33 (-28.9031, 27) -> (-22.9031, 27)
  line L34 (-27.4031, -13.5) -> (-27.4031, 25.5)
  line L35 (-30.4031, 25.5) -> (-30.4031, -13.5)
  line L36 (-34.9031, 27) -> (-28.9031, 27)
  line L37 (-33.4031, -8.5) -> (-33.4031, 25.5)
  line L38 (-31.9031, -15.5) -> (-34.9031, -15.5)
  line L39 (-31.9031, -18.5) -> (-31.9031, -15.5)
  line L40 (-37.9031, -18.5) -> (-31.9031, -18.5)
  line L41 (-37.9031, -15.5) -> (-37.9031, -18.5)
  circle C1 centre (-34.9031, -15.5) radius 3
  arc A1 centre (-34.9031, 25.5) radius 1.5 clockwise from (-36.4031, 25.5) to (-34.9031, 27)
  arc A2 centre (13.0969, 25.5) radius 1.5 clockwise from (13.0969, 27) to (14.5969, 25.5)
  arc A3 centre (13.0969, -13.5) radius 1.5 clockwise from (14.5969, -13.5) to (11.5969, -13.5)
  arc A4 centre (13.0969, 25.5) radius 1.5 clockwise from (11.5969, 25.5) to (13.0969, 27)
  arc A5 centre (7.0969, 25.5) radius 1.5 clockwise from (7.0969, 27) to (8.5969, 25.5)
  arc A6 centre (7.0969, -13.5) radius 1.5 clockwise from (8.5969, -13.5) to (5.5969, -13.5)
  arc A7 centre (7.0969, 25.5) radius 1.5 clockwise from (5.5969, 25.5) to (7.0969, 27)
  arc A8 centre (1.0969, 25.5) radius 1.5 clockwise from (1.0969, 27) to (2.5969, 25.5)
  arc A9 centre (1.0969, -13.5) radius 1.5 clockwise from (2.5969, -13.5) to (-0.4031, -13.5)
  arc A10 centre (1.0969, 25.5) radius 1.5 clockwise from (-0.4031, 25.5) to (1.0969, 27)
  arc A11 centre (-4.9031, 25.5) radius 1.5 clockwise from (-4.9031, 27) to (-3.4031, 25.5)
  arc A12 centre (-4.9031, -13.5) radius 1.5 clockwise from (-3.4031, -13.5) to (-6.4031, -13.5)
  arc A13 centre (-4.9031, 25.5) radius 1.5 clockwise from (-6.4031, 25.5) to (-4.9031, 27)
  arc A14 centre (-10.9031, 25.5) radius 1.5 clockwise from (-10.9031, 27) to (-9.4031, 25.5)
  arc A15 centre (-10.9031, -13.5) radius 1.5 clockwise from (-9.4031, -13.5) to (-12.4031, -13.5)
  arc A16 centre (-10.9031, 25.5) radius 1.5 clockwise from (-12.4031, 25.5) to (-10.9031, 27)
  arc A17 centre (-16.9031, 25.5) radius 1.5 clockwise from (-16.9031, 27) to (-15.4031, 25.5)
  arc A18 centre (-16.9031, -13.5) radius 1.5 clockwise from (-15.4031, -13.5) to (-18.4031, -13.5)
  arc A19 centre (-16.9031, 25.5) radius 1.5 clockwise from (-18.4031, 25.5) to (-16.9031, 27)
  arc A20 centre (-22.9031, 25.5) radius 1.5 clockwise from (-22.9031, 27) to (-21.4031, 25.5)
  arc A21 centre (-22.9031, -13.5) radius 1.5 clockwise from (-21.4031, -13.5) to (-24.4031, -13.5)
  arc A22 centre (-22.9031, 25.5) radius 1.5 clockwise from (-24.4031, 25.5) to (-22.9031, 27)
  arc A23 centre (-28.9031, 25.5) radius 1.5 clockwise from (-28.9031, 27) to (-27.4031, 25.5)
  arc A24 centre (-28.9031, -13.5) radius 1.5 clockwise from (-27.4031, -13.5) to (-30.4031, -13.5)
  arc A25 centre (-28.9031, 25.5) radius 1.5 clockwise from (-30.4031, 25.5) to (-28.9031, 27)
  arc A26 centre (-34.9031, 25.5) radius 1.5 clockwise from (-34.9031, 27) to (-33.4031, 25.5)
  arc A27 centre (-34.9031, -8.5) radius 1.5 clockwise from (-33.4031, -8.5) to (-36.4031, -8.5)
  point P2 (-34.9031, -15.5)
  point P76 (-34.9031, -15.5)
  point P77 (-31.9031, -15.5)
  point P80 (-37.9031, -15.5)
  point P81 (-37.9031, -15.5)
  coincident P2 P76
  coincident C1 P77
  tangent C1 L39
  perpendicular L39 L40
  coincident P80 P81
  tangent C1 L41
  perpendicular L40 L41
  horizontal L40
  tangent C1 L40
extrude "Extrude9" add sketch "Sketch12" profile of C1 L39 L40 L41 along normal blind 2
offset_faces "OffsetFaces17" distance 0.4
offset_faces "OffsetFaces18" distance 0.5
chamfer "Chamfer6" distance 1
hole "Hole2" HoleDepth 3 HoleDiameter 2.8
hole "Hole2" HoleDepth 7.375 HoleDiameter 2
sketch "Sketch13" plane through (0, 0, 31.4) normal (0, 0, 1) x axis (-1, 0, 0)
  line L1 (33.5031, -16.9) -> (36.3031, -16.9)
  line L2 (33.5031, -14.1) -> (33.5031, -16.9)
  line L3 (36.3031, -14.1) -> (33.5031, -14.1)
  line L4 (36.3031, -16.9) -> (36.3031, -14.1)
  line L5 (33.5031, -14.1) -> (36.3031, -16.9)
  line L6 (36.3031, -14.1) -> (33.5031, -16.9)
  line L7 (32.4031, -16.9) -> (37.4031, -16.9)
  line L8 (32.4031, -14.1) -> (32.4031, -16.9)
  line L9 (37.4031, -14.1) -> (32.4031, -14.1)
  line L10 (37.4031, -16.9) -> (37.4031, -14.1)
  line L11 (32.4031, -14.1) -> (37.4031, -16.9)
  line L12 (37.4031, -14.1) -> (32.4031, -16.9)
  circle C1 centre (34.9031, -15.5) radius 1.4
  circle C2 centre (34.9031, -15.5) radius 2.5
  point P7 (34.9031, -15.5)
  point P2 (34.9031, -15.5)
  point P12 (34.9031, -15.5)
  point P5 (33.5031, -14.1)
  point P6 (36.3031, -14.1)
  point P4 (33.5031, -16.9)
  point P10 (32.4031, -14.1)
  point P11 (37.4031, -14.1)
  point P9 (32.4031, -16.9)
  horizontal L1
  perpendicular L1 L2
  parallel L1 L3
  parallel L2 L4
  coincident L5 P7
  coincident L6 P7
  coincident P2 P7
  horizontal L7
  perpendicular L7 L8
  parallel L7 L9
  parallel L8 L10
  coincident L11 P12
  coincident L12 P12
  coincident P7 P12
  dimension "d143" distance P5 P6 = 2.8
  dimension "d144" distance P4 P5 = 2.8
  dimension "d145" distance P10 P11 = 5
  dimension "d146" distance P9 P10 = 2.8
extrude "Extrude10" cut sketch "Sketch13" profile of C1 L1 L2 L3 L4 L7 L9 against normal blind 0.4
extrude "Extrude11" cut sketch "Sketch13" profile of C2 L2 L4 L7 L9 against normal blind 0.2
copy_paste "CopyPaste1"
chamfer "Chamfer7" distance 0.4
chamfer "Chamfer6" distance 0.3
sketch "Sketch14" plane through (0, 0, 31.7) normal (0, 0, -1) x axis (1, 0, 0)
  line L1 (43.0097, 24.4) -> (26.9398, 24.4)
  line L2 (40.4097, 27) -> (43.0097, 24.4)
  line L3 (25.0398, 27) -> (40.4097, 27)
  line L4 (23.0398, 25) -> (25.0398, 27)
  line L5 (23.0398, -18.1302) -> (23.0398, 25)
  line L6 (22.27, -18.9) -> (23.0398, -18.1302)
  line L7 (-37.4031, -18.9) -> (22.27, -18.9)
  line L8 (-37.4719, -18.8313) -> (-37.4031, -18.9)
  line L9 (-39.6992, -21.0586) -> (-37.4719, -18.8313)
  line L10 (-39.6992, -24.0586) -> (-39.6992, -21.0586)
  line L11 (-36.5406, -20.9) -> (-39.6992, -24.0586)
  line L12 (22.957, -20.9) -> (-36.5406, -20.9)
  line L13 (24.9398, -18.9172) -> (22.957, -20.9)
  line L14 (24.9398, 22.4) -> (24.9398, -18.9172)
  line L15 (26.9398, 24.4) -> (24.9398, 22.4)
  line L16 (15.8219, -19) -> (15.8219, -25.269)
  line L17 (-35.8171, -25.269) -> (-35.8171, -19)
  line L18 (-35.8171, -19) -> (-35.8171, -25.269)
  line L19 (15.8219, -19) -> (-35.8171, -19)
  line L20 (15.8219, -25.269) -> (15.8219, -19)
  line L21 (-32.8171, -28.269) -> (12.8219, -28.269)
  line L22 (-36.5406, -20.9) -> (22.957, -20.9)
  arc A1 centre (-32.8171, -25.269) radius 3 clockwise from (-32.8171, -28.269) to (-35.8171, -25.269)
  arc A2 centre (12.8219, -25.269) radius 3 clockwise from (15.8219, -25.269) to (12.8219, -28.269)
extrude "Extrude12" add sketch "Sketch14" profile of L12 L16 L17 L18 L19 L20 L22 along normal blind 0.4
offset_faces "OffsetFaces19" distance -0.2
offset_faces "OffsetFaces20" distance -0.2
base_feature "Base Feature1"
position "Position10"
offset_faces "OffsetFaces21" distance 0.399
position "Position11"
position "Position12"
position "Position13"
position "Position14"
position "Position15"
extrude "Extrude13" add of existing geometry blind 5
draft "Draft2" "d161" 45 (= "Angle1") "d162" 0 (= "Angle2")
draft "Draft3" "d163" 45 (= "Angle1") "d164" 0 (= "Angle2")
chamfer "Chamfer8" distance 2.5
delete_face "DeleteFace12"
chamfer "Chamfer9" distance 3
delete_face "DeleteFace13"
delete_face "DeleteFace14"
delete_face "DeleteFace15"
chamfer "Chamfer10" distance 3
chamfer "Chamfer11" distance 2.5
delete_face "DeleteFace16"
chamfer "Chamfer12" distance 1
chamfer "Chamfer13" distance 1
delete_face "DeleteFace17"
delete_face "DeleteFace18"
delete_face "DeleteFace19"
delete_face "DeleteFace20"
delete_face "DeleteFace21"
offset_faces "OffsetFaces22" distance 1
delete_face "DeleteFace22"
chamfer "Chamfer14" distance 3
chamfer "Chamfer15" distance 1
chamfer "Chamfer16" distance 1
position "Position16"
work_plane "WorkPlane11"
work_plane "WorkPlane12"
position "Position17"
sketch "Sketch16" plane through (0, 0, 28.4) normal (0, 0, 1) x axis (-1, 0, 0)
  line L1 (42.8321, 29.5) -> (42.125, 29)
  line L2 (42.8321, 35) -> (42.8321, 29.5)
  line L3 (-41.3524, 35) -> (42.8321, 35)
  line L4 (-41.3524, 29.5) -> (-41.3524, 35)
  line L5 (-20.0388, 29.5) -> (-41.3524, 29.5)
  line L6 (-20.0388, -26.6201) -> (-20.0388, 29.5)
  line L7 (-16.9602, -22.3427) -> (-16.9602, -26.6671)
  line L8 (-15.3744, -20.7569) -> (-16.9602, -22.3427)
  line L9 (35.0541, -20.7569) -> (-15.3744, -20.7569)
  line L10 (36.6398, -22.3427) -> (35.0541, -20.7569)
  line L11 (36.6398, -26.6671) -> (36.6398, -22.3427)
  line L12 (39.7185, -11.482) -> (39.7185, -26.6201)
  line L13 (38.3561, -11.482) -> (39.7185, -11.482)
  line L14 (36.2703, -9.3962) -> (38.3561, -11.482)
  line L15 (36.2703, 10.8322) -> (36.2703, -9.3962)
  line L16 (38.3561, 12.918) -> (36.2703, 10.8322)
  line L17 (39.7185, 12.918) -> (38.3561, 12.918)
  line L18 (39.7185, 29) -> (39.7185, 12.918)
  line L19 (42.125, 29) -> (39.7185, 29)
  line L20 (-1.9699, 15.2588) -> (-3.4133, 17.7588)
  line L21 (-3.4133, 12.7588) -> (-1.9699, 15.2588)
  line L22 (-6.3, 12.7588) -> (-3.4133, 12.7588)
  line L23 (-7.7434, 15.2588) -> (-6.3, 12.7588)
  line L24 (-6.3, 17.7588) -> (-7.7434, 15.2588)
  line L25 (-3.4133, 17.7588) -> (-6.3, 17.7588)
  line L26 (-11.323, 14.8588) -> (-12.7664, 12.3588)
  line L27 (-8.4362, 14.8588) -> (-11.323, 14.8588)
  line L28 (-6.9929, 12.3588) -> (-8.4362, 14.8588)
  line L29 (-8.4362, 9.8588) -> (-6.9929, 12.3588)
  line L30 (-11.323, 9.8588) -> (-8.4362, 9.8588)
  line L31 (-12.7664, 12.3588) -> (-11.323, 9.8588)
  line L32 (-2.7205, 18.1588) -> (-1.2771, 15.6588)
  line L33 (-1.2771, 20.6588) -> (-2.7205, 18.1588)
  line L34 (1.6097, 20.6588) -> (-1.2771, 20.6588)
  line L35 (3.053, 18.1588) -> (1.6097, 20.6588)
  line L36 (1.6097, 15.6588) -> (3.053, 18.1588)
  line L37 (-1.2771, 15.6588) -> (1.6097, 15.6588)
  line L38 (-8.4362, 15.6588) -> (-6.9929, 18.1588)
  line L39 (-11.323, 15.6588) -> (-8.4362, 15.6588)
  line L40 (-12.7664, 18.1588) -> (-11.323, 15.6588)
  line L41 (-11.323, 20.6588) -> (-12.7664, 18.1588)
  line L42 (-8.4362, 20.6588) -> (-11.323, 20.6588)
  line L43 (-6.9929, 18.1588) -> (-8.4362, 20.6588)
  line L44 (8.076, 15.2588) -> (6.6326, 17.7588)
  line L45 (6.6326, 12.7588) -> (8.076, 15.2588)
  line L46 (3.7458, 12.7588) -> (6.6326, 12.7588)
  line L47 (2.3025, 15.2588) -> (3.7458, 12.7588)
  line L48 (3.7458, 17.7588) -> (2.3025, 15.2588)
  line L49 (6.6326, 17.7588) -> (3.7458, 17.7588)
  line L50 (7.3254, 12.3588) -> (8.7688, 9.8588)
  line L51 (8.7688, 14.8588) -> (7.3254, 12.3588)
  line L52 (11.6555, 14.8588) -> (8.7688, 14.8588)
  line L53 (13.0989, 12.3588) -> (11.6555, 14.8588)
  line L54 (11.6555, 9.8588) -> (13.0989, 12.3588)
  line L55 (8.7688, 9.8588) -> (11.6555, 9.8588)
  line L56 (18.8147, 9.0588) -> (17.3713, 6.5588)
  line L57 (21.7014, 9.0588) -> (18.8147, 9.0588)
  line L58 (23.1448, 6.5588) -> (21.7014, 9.0588)
  line L59 (21.7014, 4.0588) -> (23.1448, 6.5588)
  line L60 (18.8147, 4.0588) -> (21.7014, 4.0588)
  line L61 (17.3713, 6.5588) -> (18.8147, 4.0588)
  line L62 (23.8376, -5.4412) -> (22.3943, -7.9412)
  line L63 (26.7244, -5.4412) -> (23.8376, -5.4412)
  line L64 (28.1678, -7.9412) -> (26.7244, -5.4412)
  line L65 (26.7244, -10.4412) -> (28.1678, -7.9412)
  line L66 (23.8376, -10.4412) -> (26.7244, -10.4412)
  line L67 (22.3943, -7.9412) -> (23.8376, -10.4412)
  line L68 (13.7917, 0.3588) -> (12.3484, -2.1412)
  line L69 (16.6785, 0.3588) -> (13.7917, 0.3588)
  line L70 (18.1219, -2.1412) -> (16.6785, 0.3588)
  line L71 (16.6785, -4.6412) -> (18.1219, -2.1412)
  line L72 (13.7917, -4.6412) -> (16.6785, -4.6412)
  line L73 (12.3484, -2.1412) -> (13.7917, -4.6412)
  line L74 (1.6097, 3.2588) -> (-1.2771, 3.2588)
  line L75 (3.053, 0.7588) -> (1.6097, 3.2588)
  line L76 (1.6097, -1.7412) -> (3.053, 0.7588)
  line L77 (-1.2771, -1.7412) -> (1.6097, -1.7412)
  line L78 (-2.7205, 0.7588) -> (-1.2771, -1.7412)
  line L79 (-1.2771, 3.2588) -> (-2.7205, 0.7588)
  line L80 (-6.3, 11.9588) -> (-7.7434, 9.4588)
  line L81 (-3.4133, 11.9588) -> (-6.3, 11.9588)
  line L82 (-1.9699, 9.4588) -> (-3.4133, 11.9588)
  line L83 (-3.4133, 6.9588) -> (-1.9699, 9.4588)
  line L84 (-6.3, 6.9588) -> (-3.4133, 6.9588)
  line L85 (-7.7434, 9.4588) -> (-6.3, 6.9588)
  line L86 (-8.4362, -2.5412) -> (-11.323, -2.5412)
  line L87 (-6.9929, -5.0412) -> (-8.4362, -2.5412)
  line L88 (-8.4362, -7.5412) -> (-6.9929, -5.0412)
  line L89 (-11.323, -7.5412) -> (-8.4362, -7.5412)
  line L90 (-12.7664, -5.0412) -> (-11.323, -7.5412)
  line L91 (-11.323, -2.5412) -> (-12.7664, -5.0412)
  line L92 (-6.3, -11.2412) -> (-7.7434, -13.7412)
  line L93 (-3.4133, -11.2412) -> (-6.3, -11.2412)
  line L94 (-1.9699, -13.7412) -> (-3.4133, -11.2412)
  line L95 (-2.4276, -14.534) -> (-1.9699, -13.7412)
  line L96 (-7.2857, -14.534) -> (-2.4276, -14.534)
  line L97 (-7.7434, -13.7412) -> (-7.2857, -14.534)
  line L98 (3.7458, -5.4412) -> (2.3025, -7.9412)
  line L99 (6.6326, -5.4412) -> (3.7458, -5.4412)
  line L100 (8.076, -7.9412) -> (6.6326, -5.4412)
  line L101 (6.6326, -10.4412) -> (8.076, -7.9412)
  line L102 (3.7458, -10.4412) -> (6.6326, -10.4412)
  line L103 (2.3025, -7.9412) -> (3.7458, -10.4412)
  line L104 (22.3943, -13.7412) -> (22.852, -14.534)
  line L105 (23.8376, -11.2412) -> (22.3943, -13.7412)
  line L106 (26.7244, -11.2412) -> (23.8376, -11.2412)
  line L107 (28.1678, -13.7412) -> (26.7244, -11.2412)
  line L108 (27.71, -14.534) -> (28.1678, -13.7412)
  line L109 (22.852, -14.534) -> (27.71, -14.534)
  line L110 (18.8147, 20.6588) -> (17.3713, 18.1588)
  line L111 (21.7014, 20.6588) -> (18.8147, 20.6588)
  line L112 (23.1448, 18.1588) -> (21.7014, 20.6588)
  line L113 (21.7014, 15.6588) -> (23.1448, 18.1588)
  line L114 (18.8147, 15.6588) -> (21.7014, 15.6588)
  line L115 (17.3713, 18.1588) -> (18.8147, 15.6588)
  line L116 (28.8606, 14.8588) -> (27.4172, 12.3588)
  line L117 (31.7473, 14.8588) -> (28.8606, 14.8588)
  line L118 (33.1907, 12.3588) -> (31.7473, 14.8588)
  line L119 (31.7473, 9.8588) -> (33.1907, 12.3588)
  line L120 (28.8606, 9.8588) -> (31.7473, 9.8588)
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  point P426 (9.8398, 3.6588)
  point P431 (9.8398, 3.6588)
  point P429 (-10.2102, 23.7088)
  point P430 (29.8898, 23.7088)
  point P427 (29.8898, -16.3912)
  coincident P426 P431
  dimension "d176" distance P429 P430 = 40.1
  dimension "d177" distance P427 P430 = 40.1
extrude "Extrude1" cut sketch "Sketch16" against normal blind 4.3752
extrude "Extrude2" add blind -4.3752 Side1WallThickness 1.1
delete_face "DeleteFace5"
offset_faces "OffsetFaces2" distance -0.1
chamfer "Chamfer1" distance 1
offset_faces "OffsetFaces3" distance -2.291
fillet "Fillet1" radius 4
move_face "MoveFace6"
